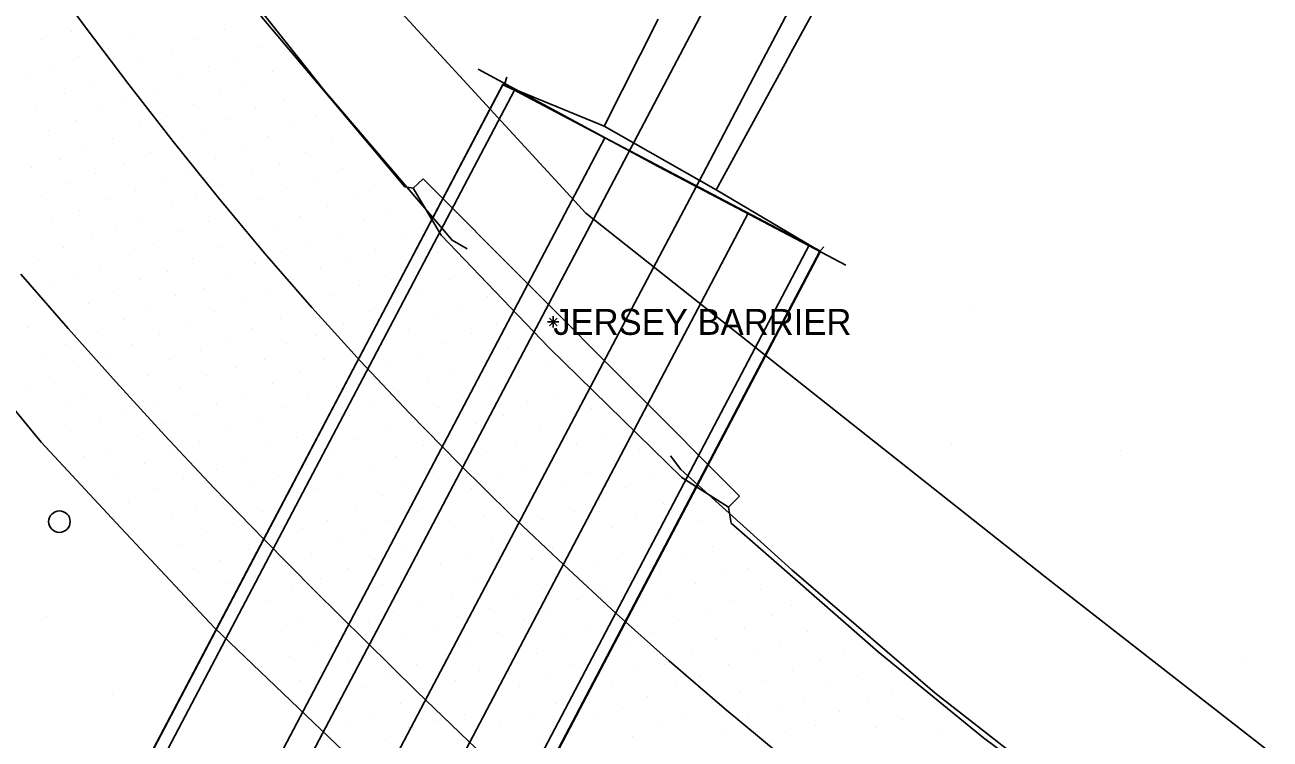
# Model space of a CAD drawing. Extents: x 1732346 to 1733076, y 467730 to 468633.
# Drawn here: x 1732739.5 to 1732826.1, y 468139.6 to 468189.3 of the extents above; entities that cross this region are included whole.
import ezdxf

# ---------------------------------------------------------------- set-up
doc = ezdxf.new("R2010")
doc.units = 0
for name, color, linetype in [('Default', 7, 'Continuous'), ('S_Bridge_BoxCulvert', 7, 'Continuous'), ('S_Ground_Elevation', 7, 'Continuous'), ('S_Ground_LevelString', 7, 'Continuous'), ('S_Ground_SpotElevation', 7, 'Continuous'), ('S_Guardrail_Beam', 7, 'Continuous'), ('S_Guardrail_JerseyBarrier', 7, 'Continuous'), ('S_Misc_MiscItems', 7, 'Continuous'), ('S_Railroad_Tracks', 7, 'Continuous'), ('S_Roadway_Edge_Pavement', 7, 'Continuous'), ('S_Roadway_Painted_Lines', 7, 'Continuous'), ('S_Text', 7, 'Continuous'), ('S_Traffic_Posts', 7, 'Continuous'), ('S_Trees_Bush_Line', 7, 'Continuous'), ('TopoDOT Temp', 7, 'Continuous')]:
    doc.layers.add(name, color=color, linetype=linetype)

# ---------------------------------------------------------------- blocks, each defined once
blk = doc.blocks.new('POINT_DISPLAY')
at = {"layer": 'Default'}
blk.add_line((0, 0), (0, 0), dxfattribs=at)

msp = doc.modelspace()

# ---------------------------------------------------------------- linework, layer by layer
at = {"layer": 'S_Bridge_BoxCulvert'}
for p, q in [((1732639.349, 467931.595), (1732772.729, 468185.159)), ((1732639.356, 467931.621), (1732772.736, 468185.185)), ((1732640.157, 467931.201), (1732773.537, 468184.766)), ((1732646.436, 467927.898), (1732779.815, 468181.463)), ((1732656.397, 467922.658), (1732789.777, 468176.223)), ((1732660.637, 467920.428), (1732794.017, 468173.993)), ((1732661.386, 467920.002), (1732794.766, 468173.567)), ((1732661.436, 467920.006), (1732794.816, 468173.571))]:
    msp.add_line(p, q, dxfattribs=at)
msp.add_lwpolyline([(1732794.766, 468173.567), (1732794.816, 468173.571), (1732794.017, 468173.993), (1732789.777, 468176.223), (1732779.815, 468181.463), (1732773.537, 468184.766), (1732772.736, 468185.185), (1732772.729, 468185.159)], dxfattribs=at)
at = {"layer": 'S_Ground_Elevation'}
for points in [[(1732787.556, 468177.841), (1732792.344, 468186.62), (1732792.746, 468187.357), (1732797.534, 468196.136)], [(1732783.528, 468189.713), (1732779.763, 468182.278)]]:
    msp.add_lwpolyline(points, dxfattribs=at)
at = {"layer": 'S_Ground_LevelString'}
for p, q in [((1732779.763, 468182.278), (1732772.729, 468185.159)), ((1732772.998, 468185.664), (1732772.868, 468185.232))]:
    msp.add_line(p, q, dxfattribs=at)
for points in [[(1732796.575, 468172.591), (1732794.894, 468173.473), (1732783.527, 468179.451), (1732771.014, 468186.238)], [(1732794.766, 468173.567), (1732794.795, 468173.542), (1732794.017, 468173.993), (1732773.537, 468184.766), (1732772.725, 468185.151), (1732772.729, 468185.159)], [(1732779.763, 468182.278), (1732787.556, 468177.841), (1732794.766, 468173.567)], [(1732794.766, 468173.567), (1732794.853, 468173.67), (1732795.044, 468173.866)]]:
    msp.add_lwpolyline(points, dxfattribs=at)
at = {"layer": 'S_Ground_SpotElevation'}
msp.add_line((1732794.894, 468173.473), (1732794.894, 468173.473), dxfattribs=at)
at = {"layer": 'S_Guardrail_Beam'}
for points in [[(1732755.07, 468191.369), (1732760.346, 468184.703), (1732769.19, 468174.338), (1732770.25, 468173.744)], [(1732784.382, 468159.331), (1732785.099, 468158.378), (1732792.825, 468151.4), (1732802.762, 468142.865), (1732814.72, 468133.514), (1732825.815, 468125.941), (1732836.325, 468119.351), (1732849.385, 468111.474), (1732864.593, 468102.997), (1732885.992, 468092.153), (1732906.222, 468082.865), (1732922.81, 468075.745), (1732936.425, 468070.374), (1732944.226, 468067.605), (1732958.088, 468062.882), (1732972.686, 468058.256), (1732988.331, 468053.793), (1732995.824, 468051.775), (1733007.391, 468048.851), (1733017.284, 468046.625), (1733034.703, 468042.774), (1733054.044, 468038.708), (1733073.975, 468034.234)]]:
    msp.add_lwpolyline(points, dxfattribs=at)
at = {"layer": 'S_Guardrail_JerseyBarrier'}
msp.add_lwpolyline([(1732767.184, 468178.606), (1732766.482, 468177.955), (1732768.426, 468174.677), (1732775.933, 468166.841), (1732785.177, 468157.836), (1732788.413, 468155.768), (1732789.172, 468156.53), (1732767.184, 468178.606)], dxfattribs=at)
at = {"layer": 'S_Misc_MiscItems'}
for p, q in [((1732776.62, 468168.652), (1732775.834, 468168.652)), ((1732776.489, 468168.39), (1732775.965, 468168.914)), ((1732776.489, 468168.914), (1732775.965, 468168.39)), ((1732776.227, 468169.045), (1732776.227, 468168.259))]:
    msp.add_line(p, q, dxfattribs=at)
at = {"layer": 'S_Railroad_Tracks'}
for points in [[(1732794.809, 468194.505), (1732790.156, 468185.654), (1732786.365, 468178.442), (1732781.701, 468169.596), (1732777.038, 468160.75), (1732772.374, 468151.904), (1732767.711, 468143.058), (1732763.047, 468134.212), (1732758.384, 468125.366), (1732753.721, 468116.52), (1732749.057, 468107.674), (1732744.394, 468098.828), (1732739.73, 468089.982), (1732735.067, 468081.136), (1732730.403, 468072.29), (1732725.74, 468063.444), (1732721.076, 468054.598), (1732716.413, 468045.752), (1732711.749, 468036.906), (1732707.086, 468028.06), (1732702.422, 468019.214), (1732697.759, 468010.368), (1732693.095, 468001.522), (1732688.432, 467992.676)], [(1732680.786, 467989.136), (1732685.443, 467997.986), (1732690.1, 468006.835), (1732694.757, 468015.685), (1732699.414, 468024.534), (1732704.07, 468033.384), (1732708.727, 468042.233), (1732713.384, 468051.083), (1732718.041, 468059.932), (1732722.698, 468068.782), (1732727.355, 468077.631), (1732732.012, 468086.481), (1732736.669, 468095.33), (1732741.325, 468104.18), (1732745.982, 468113.029), (1732750.639, 468121.879), (1732755.296, 468130.728), (1732759.953, 468139.578), (1732764.61, 468148.427), (1732769.267, 468157.277), (1732773.924, 468166.126), (1732778.581, 468174.976), (1732783.237, 468183.825), (1732787.789, 468192.475)]]:
    msp.add_lwpolyline(points, dxfattribs=at)
at = {"layer": 'S_Roadway_Edge_Pavement'}
for p, q in [((1732765.901, 468178.051), (1732766.482, 468177.955)), ((1732788.591, 468154.667), (1732788.413, 468155.768))]:
    msp.add_line(p, q, dxfattribs=at)
for points in [[(1732739.525, 468213.056), (1732745.09, 468204.452), (1732749.849, 468197.779), (1732756.091, 468189.713), (1732760.997, 468183.883), (1732765.901, 468178.051)], [(1732823.007, 468089.57), (1732821.659, 468091.736), (1732813.423, 468097.407), (1732807.383, 468101.566), (1732799.356, 468107.529), (1732792.806, 468112.395), (1732784.933, 468118.56), (1732778.351, 468123.714), (1732770.846, 468130.322), (1732766.796, 468133.889), (1732759.562, 468140.794), (1732752.667, 468147.374), (1732745.846, 468154.686), (1732740.622, 468160.287), (1732734.263, 468168.005), (1732729.679, 468173.568), (1732723.729, 468181.605), (1732721.39, 468184.764), (1732715.912, 468193.131)], [(1732837.239, 468118.646), (1732823.774, 468127.095), (1732813.991, 468133.891), (1732806.132, 468139.717), (1732798.824, 468145.7), (1732788.591, 468154.667)]]:
    msp.add_lwpolyline(points, dxfattribs=at)
at = {"layer": 'S_Roadway_Painted_Lines'}
for points in [[(1732791.946, 468138.611), (1732788.116, 468141.801), (1732784.299, 468145.073), (1732780.609, 468148.376), (1732776.957, 468151.751), (1732773.273, 468155.24), (1732769.714, 468158.758), (1732766.226, 468162.315), (1732762.824, 468165.916), (1732759.452, 468169.656), (1732756.159, 468173.425), (1732752.942, 468177.278), (1732749.803, 468181.202), (1732746.713, 468185.168), (1732743.692, 468189.171), (1732740.641, 468193.336)], [(1732825.966, 468093.946), (1732820.204, 468097.932), (1732816.137, 468100.822), (1732812.193, 468103.722), (1732808.216, 468106.752), (1732804.26, 468109.866), (1732800.477, 468112.919), (1732796.559, 468116.159), (1732792.712, 468119.384), (1732788.887, 468122.626), (1732785.092, 468125.927), (1732781.349, 468129.243), (1732777.649, 468132.626), (1732773.968, 468136.047), (1732770.341, 468139.484), (1732766.734, 468142.956), (1732763.187, 468146.439), (1732759.62, 468149.983), (1732756.116, 468153.527), (1732752.639, 468157.117), (1732749.224, 468160.76), (1732745.832, 468164.467), (1732742.496, 468168.204), (1732739.21, 468171.965)]]:
    msp.add_lwpolyline(points, dxfattribs=at)
at = {"layer": 'S_Traffic_Posts'}
msp.add_circle((1732741.892, 468154.764), 0.749, dxfattribs=at)
at = {"layer": 'S_Trees_Bush_Line'}
msp.add_lwpolyline([(1733076.457, 468046.745), (1733041.715, 468052.429), (1733015.862, 468057.837), (1732966.818, 468070.303), (1732920.395, 468084.59), (1732889.536, 468097.751), (1732857.392, 468112.01), (1732836.107, 468130.901), (1732810.433, 468150.929), (1732778.494, 468176.218), (1732763.066, 468193.027), (1732750.601, 468208.657)], dxfattribs=at)
at = {"layer": 'TopoDOT Temp'}
for p, q in [((1732792.746, 468187.357), (1732792.746, 468187.357)), ((1732792.344, 468186.62), (1732792.344, 468186.62)), ((1732790.156, 468185.654), (1732790.156, 468185.654)), ((1732783.237, 468183.825), (1732783.237, 468183.825)), ((1732779.763, 468182.278), (1732779.763, 468182.278)), ((1732779.763, 468182.278), (1732779.763, 468182.278)), ((1732786.365, 468178.442), (1732786.365, 468178.442)), ((1732787.556, 468177.841), (1732787.556, 468177.841)), ((1732787.556, 468177.841), (1732787.556, 468177.841)), ((1732778.581, 468174.976), (1732778.581, 468174.976)), ((1732781.701, 468169.596), (1732781.701, 468169.596)), ((1732773.924, 468166.126), (1732773.924, 468166.126)), ((1732777.038, 468160.75), (1732777.038, 468160.75)), ((1732769.267, 468157.277), (1732769.267, 468157.277)), ((1732772.374, 468151.904), (1732772.374, 468151.904)), ((1732764.61, 468148.427), (1732764.61, 468148.427)), ((1732767.711, 468143.058), (1732767.711, 468143.058))]:
    msp.add_line(p, q, dxfattribs=at)

# ---------------------------------------------------------------- block references
at = {"layer": 'S_Ground_SpotElevation'}
for p in [(1732742.723, 468188.823), (1732747.028, 468188.676), (1732753.371, 468189.009), (1732740.623, 468188.308), (1732745.31, 468187.678), (1732751.468, 468188.275), (1732755.699, 468187.762), (1732743.226, 468187.147), (1732747.675, 468186.762), (1732749.679, 468187.534), (1732754.267, 468186.891), (1732741.514, 468186.416), (1732752.225, 468186.387), (1732756.681, 468186.043), (1732739.568, 468185.692), (1732744.069, 468185.332), (1732746.106, 468185.709), (1732750.474, 468185.637), (1732754.883, 468185.298), (1732742.265, 468184.542), (1732746.53, 468184.201), (1732748.718, 468184.751), (1732753.043, 468184.543), (1732757.498, 468184.135), (1732740.291, 468183.724), (1732744.842, 468183.428), (1732751.186, 468183.791), (1732755.538, 468183.501), (1732743.043, 468182.636), (1732749.345, 468183.033), (1732753.734, 468182.732), (1732759.718, 468182.959), (1732741.121, 468181.958), (1732747.563, 468182.233), (1732751.86, 468181.941), (1732756.387, 468181.531), (1732758.179, 468182.334), (1732743.786, 468180.824), (1732745.608, 468181.426), (1732750.116, 468181.133), (1732754.611, 468180.725), (1732760.846, 468181.135), (1732741.994, 468179.974), (1732748.209, 468180.409), (1732752.715, 468180.028), (1732758.972, 468180.458), (1732739.967, 468179.368), (1732744.403, 468178.959), (1732746.406, 468179.701), (1732750.932, 468179.122), (1732755.293, 468178.983), (1732757.192, 468179.668), (1732761.583, 468179.324), (1732783.527, 468179.451), (1732742.607, 468178.249), (1732748.955, 468178.608), (1732753.133, 468178.181), (1732759.816, 468178.536), (1732763.788, 468178.173), (1732740.652, 468177.354), (1732747.166, 468177.763), (1732751.418, 468177.56), (1732757.711, 468177.951), (1732762.321, 468177.532), (1732743.288, 468176.414), (1732745.193, 468177.147), (1732749.728, 468176.704), (1732754.036, 468176.412), (1732755.944, 468177.135), (1732760.527, 468176.714), (1732764.918, 468176.403), (1732741.412, 468175.654), (1732747.672, 468175.839), (1732752.271, 468175.668), (1732758.643, 468175.998), (1732763.071, 468175.681), (1732745.839, 468175.317), (1732750.377, 468174.916), (1732756.778, 468175.261), (1732761.283, 468174.835), (1732767.239, 468174.974), (1732742.207, 468173.798), (1732744.135, 468174.444), (1732748.439, 468174.108), (1732752.944, 468173.846), (1732754.78, 468174.483), (1732759.266, 468174.218), (1732765.69, 468174.546), (1732740.458, 468173.006), (1732746.779, 468173.351), (1732751.132, 468173.07), (1732757.326, 468173.47), (1732761.85, 468173.084), (1732763.892, 468173.704), (1732768.156, 468173.455), (1732744.728, 468172.493), (1732749.38, 468172.16), (1732755.537, 468172.696), (1732760.031, 468172.35), (1732766.481, 468172.629), (1732742.952, 468171.755), (1732747.435, 468171.573), (1732753.808, 468171.769), (1732758.191, 468171.612), (1732762.778, 468171.157), (1732764.594, 468171.905), (1732769.023, 468171.58), (1732741.249, 468171.111), (1732745.661, 468170.702), (1732749.95, 468170.458), (1732752.01, 468171.009), (1732756.498, 468170.712), (1732760.772, 468170.506), (1732767.17, 468170.805), (1732771.648, 468170.453), (1732743.897, 468169.917), (1732748.164, 468169.678), (1732754.599, 468170.039), (1732758.995, 468169.714), (1732765.312, 468170.019), (1732769.662, 468169.79), (1732805.529, 468169.721), (1732741.517, 468169.062), (1732746.445, 468168.844), (1732750.735, 468168.645), (1732752.686, 468169.345), (1732757.23, 468168.891), (1732761.616, 468168.566), (1732763.425, 468169.351), (1732767.947, 468168.895), (1732772.254, 468168.573), (1732739.689, 468168.264), (1732744.525, 468168.015), (1732748.871, 468167.796), (1732755.323, 468168.174), (1732759.721, 468167.733), (1732766.156, 468168.12), (1732770.556, 468167.825), (1732742.298, 468167.091), (1732746.956, 468167.07), (1732753.505, 468167.337), (1732757.707, 468167.142), (1732764.243, 468167.462), (1732768.554, 468167.155), (1732774.857, 468167.287), (1732740.667, 468166.187), (1732745.357, 468166.251), (1732749.534, 468166.032), (1732751.671, 468166.642), (1732756.171, 468166.059), (1732760.225, 468166.04), (1732762.146, 468166.561), (1732766.801, 468166.387), (1732773.047, 468166.775), (1732743.198, 468165.535), (1732754.177, 468165.502), (1732758.646, 468165.11), (1732764.81, 468165.702), (1732769.363, 468165.304), (1732771.313, 468165.865), (1732775.746, 468165.578), (1732741.205, 468164.783), (1732747.999, 468164.924), (1732752.1, 468164.899), (1732756.715, 468164.356), (1732763.076, 468164.88), (1732767.562, 468164.489), (1732773.779, 468164.883), (1732739.802, 468163.915), (1732743.72, 468163.637), (1732745.986, 468163.986), (1732750.301, 468164.048), (1732754.819, 468163.678), (1732761.159, 468164.15), (1732765.439, 468163.816), (1732769.937, 468163.476), (1732772.076, 468164.088), (1732776.555, 468163.697), (1732777.949, 468164.162), (1732742.381, 468162.936), (1732748.409, 468163.029), (1732752.795, 468163.01), (1732757.396, 468162.685), (1732759.22, 468163.33), (1732763.807, 468163.045), (1732768.279, 468162.677), (1732774.466, 468163.114), (1732778.909, 468162.631), (1732744.746, 468161.634), (1732746.46, 468162.26), (1732751.317, 468162.126), (1732755.744, 468161.844), (1732762.028, 468162.17), (1732766.386, 468161.951), (1732772.776, 468162.151), (1732777.127, 468161.964), (1732742.674, 468161.08), (1732747.313, 468160.778), (1732749.235, 468161.594), (1732753.732, 468161.217), (1732760.02, 468161.562), (1732764.647, 468161.094), (1732769.067, 468160.793), (1732770.796, 468161.605), (1732775.369, 468161.171), (1732751.628, 468160.337), (1732756.3, 468160.093), (1732758.38, 468160.588), (1732762.605, 468160.475), (1732767.179, 468160.051), (1732773.621, 468160.29), (1732777.851, 468160.113), (1732779.83, 468160.714), (1732803.948, 468160.22), (1732743.633, 468159.315), (1732745.377, 468159.814), (1732749.794, 468159.46), (1732754.624, 468159.218), (1732760.672, 468159.733), (1732765.279, 468159.307), (1732771.605, 468159.61), (1732776.133, 468159.286), (1732782.254, 468159.78), (1732815.697, 468159.683), (1732747.808, 468158.82), (1732752.801, 468158.368), (1732759.071, 468158.759), (1732763.54, 468158.536), (1732769.756, 468158.86), (1732774.099, 468158.656), (1732778.72, 468158.214), (1732780.505, 468158.932), (1732746.021, 468158.013), (1732750.533, 468157.769), (1732755.373, 468157.397), (1732757.15, 468157.986), (1732761.501, 468157.803), (1732766.029, 468157.489), (1732767.901, 468158.13), (1732772.436, 468157.811), (1732776.862, 468157.481), (1732783.199, 468157.769), (1732748.687, 468157.093), (1732753.329, 468156.69), (1732759.615, 468157.033), (1732764.331, 468156.61), (1732770.554, 468157.042), (1732774.945, 468156.728), (1732781.252, 468157.16), (1732785.558, 468156.457), (1732746.692, 468156.083), (1732751.379, 468155.894), (1732757.603, 468156.369), (1732762.449, 468155.845), (1732768.612, 468156.406), (1732772.961, 468155.943), (1732779.47, 468156.308), (1732783.867, 468156.039), (1732749.707, 468155.246), (1732756.031, 468155.501), (1732760.544, 468154.866), (1732764.834, 468154.845), (1732766.762, 468155.484), (1732771.368, 468155.091), (1732775.507, 468154.883), (1732777.712, 468155.45), (1732781.982, 468155.31), (1732786.511, 468154.812), (1732752.084, 468154.099), (1732754.02, 468154.635), (1732758.778, 468154.281), (1732763.193, 468153.979), (1732769.344, 468154.431), (1732773.942, 468153.939), (1732780.245, 468154.331), (1732784.73, 468154.075), (1732750.383, 468153.178), (1732756.556, 468153.732), (1732761.226, 468153.374), (1732767.623, 468153.685), (1732771.976, 468153.313), (1732776.154, 468152.963), (1732778.218, 468153.819), (1732782.909, 468153.174), (1732787.294, 468153.023), (1732755.022, 468152.802), (1732759.4, 468152.534), (1732763.813, 468152.132), (1732765.745, 468152.917), (1732770.195, 468152.538), (1732774.705, 468152.158), (1732781.031, 468152.542), (1732785.45, 468152.208), (1732751.209, 468151.488), (1732753.067, 468152.032), (1732757.634, 468151.719), (1732761.961, 468151.519), (1732768.41, 468151.781), (1732772.549, 468151.588), (1732779.07, 468151.883), (1732783.588, 468151.333), (1732789.831, 468151.537), (1732753.74, 468150.451), (1732755.539, 468150.857), (1732760.034, 468150.821), (1732764.387, 468150.412), (1732766.254, 468151.027), (1732770.667, 468150.818), (1732777.258, 468151.1), (1732781.589, 468150.861), (1732786.088, 468150.431), (1732788.006, 468151.188), (1732758.122, 468149.982), (1732769.146, 468149.766), (1732773.557, 468149.65), (1732775.457, 468150.167), (1732779.886, 468149.986), (1732784.293, 468149.694), (1732790.604, 468150.055), (1732756.259, 468149.262), (1732762.833, 468149.464), (1732767.048, 468149.199), (1732771.768, 468148.735), (1732777.938, 468149.315), (1732782.443, 468148.931), (1732788.784, 468149.288), (1732792.826, 468148.911), (1732740.973, 468148.155), (1732754.499, 468148.539), (1732758.738, 468148.073), (1732761.003, 468148.534), (1732765.137, 468148.463), (1732769.566, 468148.177), (1732774.184, 468147.864), (1732775.945, 468148.626), (1732780.712, 468148.016), (1732784.969, 468147.876), (1732786.897, 468148.496), (1732791.384, 468148.202), (1732757.311, 468147.205), (1732763.416, 468147.736), (1732767.962, 468147.205), (1732772.375, 468147.08), (1732778.766, 468147.339), (1732783.229, 468147.049), (1732789.512, 468147.405), (1732793.914, 468147.092), (1732759.612, 468146.277), (1732761.701, 468146.813), (1732765.978, 468146.702), (1732770.434, 468146.121), (1732776.864, 468146.653), (1732781.258, 468146.336), (1732787.604, 468146.595), (1732791.973, 468146.375), (1732757.901, 468145.355), (1732764.297, 468145.755), (1732768.768, 468145.488), (1732773.044, 468145.248), (1732775.083, 468145.59), (1732779.463, 468145.515), (1732785.911, 468145.777), (1732790.202, 468145.607), (1732796.423, 468145.766), (1732824.062, 468145.211), (1732762.025, 468145.06), (1732766.749, 468144.84), (1732771.09, 468144.407), (1732777.629, 468144.837), (1732782.08, 468144.452), (1732784.013, 468144.811), (1732788.42, 468144.827), (1732792.869, 468144.439), (1732794.782, 468145.141), (1732758.675, 468143.714), (1732760.076, 468144.27), (1732764.667, 468144.025), (1732769.419, 468143.743), (1732775.769, 468144.006), (1732780.278, 468143.64), (1732786.466, 468143.986), (1732791.017, 468143.745), (1732797.38, 468143.962), (1732745.584, 468142.723), (1732762.958, 468143.261), (1732767.617, 468142.902), (1732773.891, 468143.308), (1732778.274, 468143.053), (1732782.806, 468142.631), (1732784.699, 468143.336), (1732789.191, 468142.928), (1732795.485, 468143.353), (1732799.851, 468142.783), (1732761.23, 468142.371), (1732765.63, 468142.085), (1732772.129, 468142.488), (1732776.456, 468142.094), (1732781.049, 468141.802), (1732787.296, 468142.167), (1732793.604, 468142.503), (1732798.119, 468142.179), (1732763.486, 468141.124), (1732767.986, 468140.938), (1732770.038, 468141.337), (1732774.66, 468141.414), (1732779.109, 468141.065), (1732785.229, 468141.175), (1732789.838, 468141.131), (1732791.85, 468141.672), (1732796.149, 468141.557), (1732800.512, 468140.981), (1732761.878, 468140.725), (1732766.184, 468140.414), (1732772.573, 468140.783), (1732777.347, 468140.063), (1732783.516, 468140.737), (1732787.974, 468140.259), (1732792.378, 468140.103), (1732794.431, 468140.618), (1732798.629, 468140.438), (1732803.28, 468140.045), (1732764.586, 468139.642), (1732770.969, 468139.747), (1732775.223, 468139.725), (1732781.724, 468139.811)]:
    msp.add_blockref('POINT_DISPLAY', p, dxfattribs=at)

# ---------------------------------------------------------------- texts
at = {"layer": 'S_Text'}
msp.add_text('JERSEY BARRIER', height=1.8, dxfattribs=at).set_placement((1732776.227, 468167.752))

doc.saveas('drawing.dxf')
